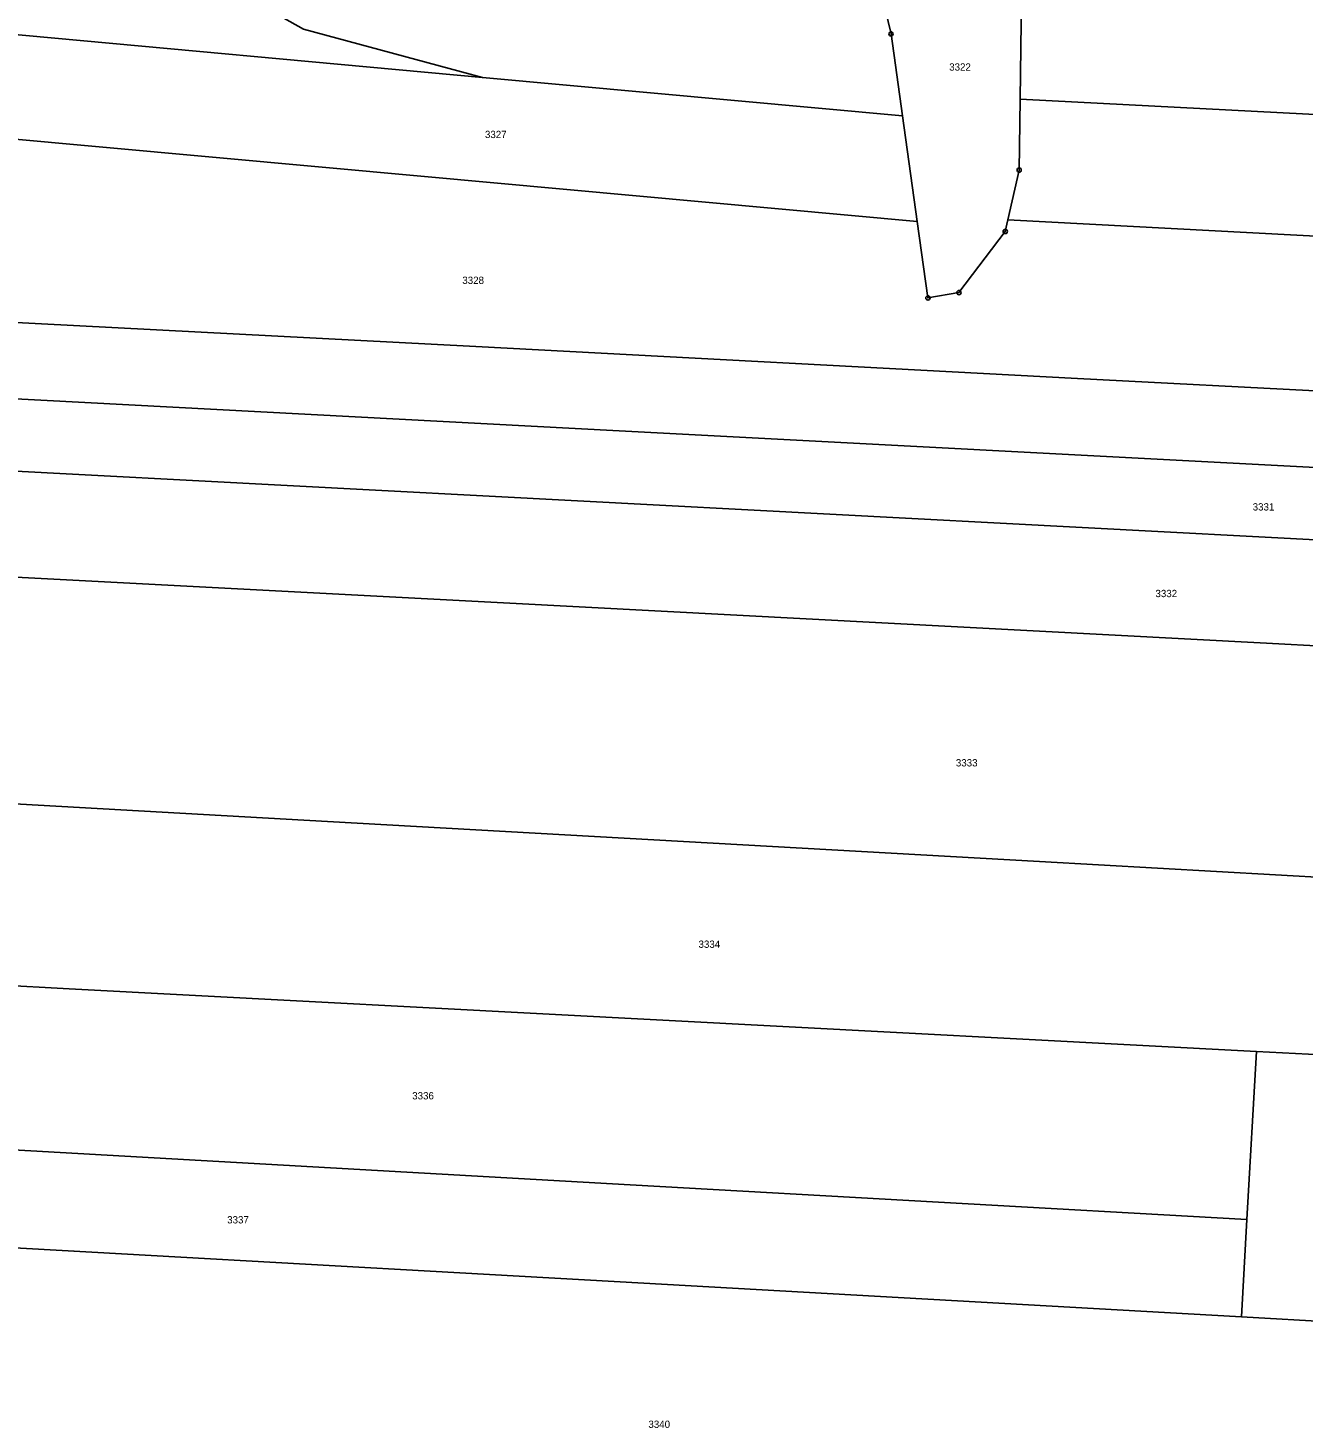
# Model space of a CAD drawing. Extents: x -618848 to -615803, y -1044450 to -1042254.
# Drawn here: x -617807.4 to -617509.9, y -1044029.5 to -1043703.1 of the extents above; entities that cross this region are included whole.
import ezdxf

# ---------------------------------------------------------------- set-up
doc = ezdxf.new("R2010")
doc.units = 0
doc.header["$LTSCALE"] = 0.68
doc.layers.add('1', color=7, linetype='Continuous', lineweight=25)
doc.layers.add('8', color=7, linetype='Continuous', lineweight=25)
doc.layers.add('2', color=7, linetype='Continuous')

msp = doc.modelspace()

# ---------------------------------------------------------------- linework, layer by layer
at = {"layer": '1'}
for p, q in [((-617794.1, -1043674.75), (-617743.08, -1043703.31)), ((-617606.05, -1043704.44), (-617609.48, -1043690.18)), ((-617575.93, -1043719.64), (-617575.55, -1043690.77)), ((-617701.33, -1043714.6), (-617823.04, -1043703.45)), ((-617743.08, -1043703.31), (-617701.33, -1043714.6)), ((-617603.38, -1043723.56), (-617606.05, -1043704.44)), ((-617701.33, -1043714.6), (-617603.38, -1043723.56)), ((-617576.15, -1043736.21), (-617575.93, -1043719.64)), ((-617456.16, -1043725.95), (-617575.93, -1043719.64)), ((-617603.38, -1043723.56), (-617599.93, -1043748.22)), ((-617714.88, -1043737.7), (-617829.83, -1043727.19)), ((-617599.93, -1043748.22), (-617714.88, -1043737.7)), ((-617578.78, -1043747.83), (-617576.15, -1043736.21)), ((-617599.93, -1043748.22), (-617597.45, -1043766)), ((-617590.22, -1043764.77), (-617579.39, -1043750.52)), ((-617579.39, -1043750.52), (-617578.78, -1043747.83)), ((-617578.78, -1043747.83), (-617420.21, -1043756.19)), ((-617597.45, -1043766), (-617590.22, -1043764.77)), ((-617702.9, -1043777.37), (-617843.3, -1043769.96)), ((-617562.51, -1043784.78), (-617702.9, -1043777.37)), ((-617422.11, -1043792.19), (-617562.51, -1043784.78)), ((-617850.05, -1043787.45), (-617669.49, -1043796.98)), ((-617669.49, -1043796.98), (-617488.93, -1043806.51)), ((-617679.16, -1043813.31), (-617857.25, -1043803.91)), ((-617501.06, -1043822.71), (-617679.16, -1043813.31)), ((-617870, -1043827.96), (-617694.98, -1043837.2)), ((-617694.98, -1043837.2), (-617519.96, -1043846.44)), ((-617519.96, -1043846.44), (-617344.93, -1043855.67)), ((-617737.52, -1043888.11), (-617903.65, -1043878.76)), ((-617571.39, -1043897.46), (-617737.52, -1043888.11)), ((-617405.26, -1043906.81), (-617571.39, -1043897.46)), ((-617936.21, -1043919.8), (-617797.75, -1043927.11)), ((-617797.75, -1043927.11), (-617659.28, -1043934.42)), ((-617659.28, -1043934.42), (-617520.82, -1043941.73)), ((-617520.82, -1043941.73), (-617523.02, -1043980.91)), ((-617520.82, -1043941.73), (-617407.56, -1043947.71)), ((-617666.94, -1043972.8), (-617810.87, -1043964.7)), ((-617523.02, -1043980.91), (-617666.94, -1043972.8)), ((-617524.29, -1044003.61), (-617523.02, -1043980.91)), ((-617816.94, -1043987.14), (-617670.61, -1043995.37)), ((-617670.61, -1043995.37), (-617524.29, -1044003.61)), ((-617524.29, -1044003.61), (-617334.48, -1044014.29))]:
    msp.add_line(p, q, dxfattribs=at)
at = {"layer": '8'}
for centre, radius in [((-617606.05, -1043704.4399), 0.5), ((-617606.05, -1043704.4399), 0.0303), ((-617576.15, -1043736.2099), 0.5), ((-617576.15, -1043736.2099), 0.0303), ((-617579.39, -1043750.5199), 0.5), ((-617579.39, -1043750.5199), 0.0303), ((-617597.45, -1043765.9999), 0.5), ((-617597.45, -1043765.9999), 0.0303), ((-617590.22, -1043764.7699), 0.5), ((-617590.22, -1043764.7699), 0.0303)]:
    msp.add_circle(centre, radius, dxfattribs=at)

# ---------------------------------------------------------------- texts
at = {"layer": '2'}
for s, p in [('3322', (-617592.48, -1043713.005)), ('3327', (-617700.78, -1043728.735)), ('3328', (-617706.06, -1043762.745)), ('3331', (-617521.68, -1043815.585)), ('3332', (-617544.36, -1043835.785)), ('3333', (-617590.92, -1043875.265)), ('3334', (-617650.96, -1043917.565)), ('3336', (-617717.75, -1043952.915)), ('3337', (-617760.92, -1043981.835)), ('3340', (-617662.65, -1044029.515))]:
    msp.add_text(s, height=1.7, dxfattribs=at).set_placement(p)

doc.saveas('drawing.dxf')
